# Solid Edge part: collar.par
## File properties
Title: Collar
Author: Deepak Maini
Template: Normal.par
Last saved by: Robert a Rhodes jr
Revision: 6
Application: Solid Edge
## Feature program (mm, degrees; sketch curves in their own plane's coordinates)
sketch for "unnamed RevolvedProtrusion 1" plane through (0, 0, 0) normal (0, -1, 0) x-axis (1, 0, 0)
  line (6.5405, -15.9527) -> (9.1186, -15.9527)
  line (9.1186, -15.9527) -> (9.1186, -36.5775)
  line (9.1186, -36.5775) -> (6.5405, -36.5775)
  line (6.5405, -15.9527) -> (6.5405, -36.5775)
revolve "unnamed RevolvedProtrusion 1" add finite 360 deg
sketch for "unnamed Cutout 1" plane through (0, 0, 0) normal (0, -1, 0) x-axis (1, 0, 0)
  line (-1.1811, -15.9527) -> (1.1811, -15.9527)
  line (1.1811, -15.9527) -> (1.1811, -19.1277)
  line (1.1811, -19.1277) -> (-1.1811, -19.1277)
  line (-1.1811, -19.1277) -> (-1.1811, -15.9527)
extrude "unnamed Cutout 1" cut finite 50.8 symmetric
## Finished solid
Body 1: solid body, 11 faces, 26 edges, 16 vertices.
  Faces by surface: plane 9, cylinder 2
  Edges by curve: line 16, circle 10
Bounding box of the edges (mm): 18.237 x 18.237 x 20.625, from (-9.1186, -9.1186, -36.5775) to (9.1186, 9.1186, -15.9527).
Cylindrical faces by radius (mm): R6.5405 x1, R9.1186 x1
Planar faces by outward normal: +x 2, +z 4, -x 2, -z 1
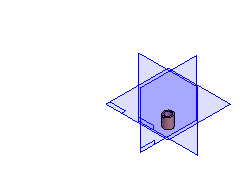
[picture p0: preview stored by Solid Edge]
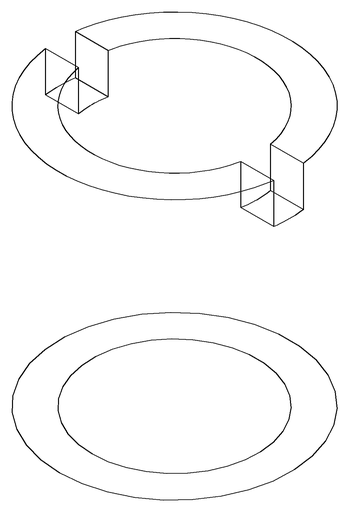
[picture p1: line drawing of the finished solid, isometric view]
